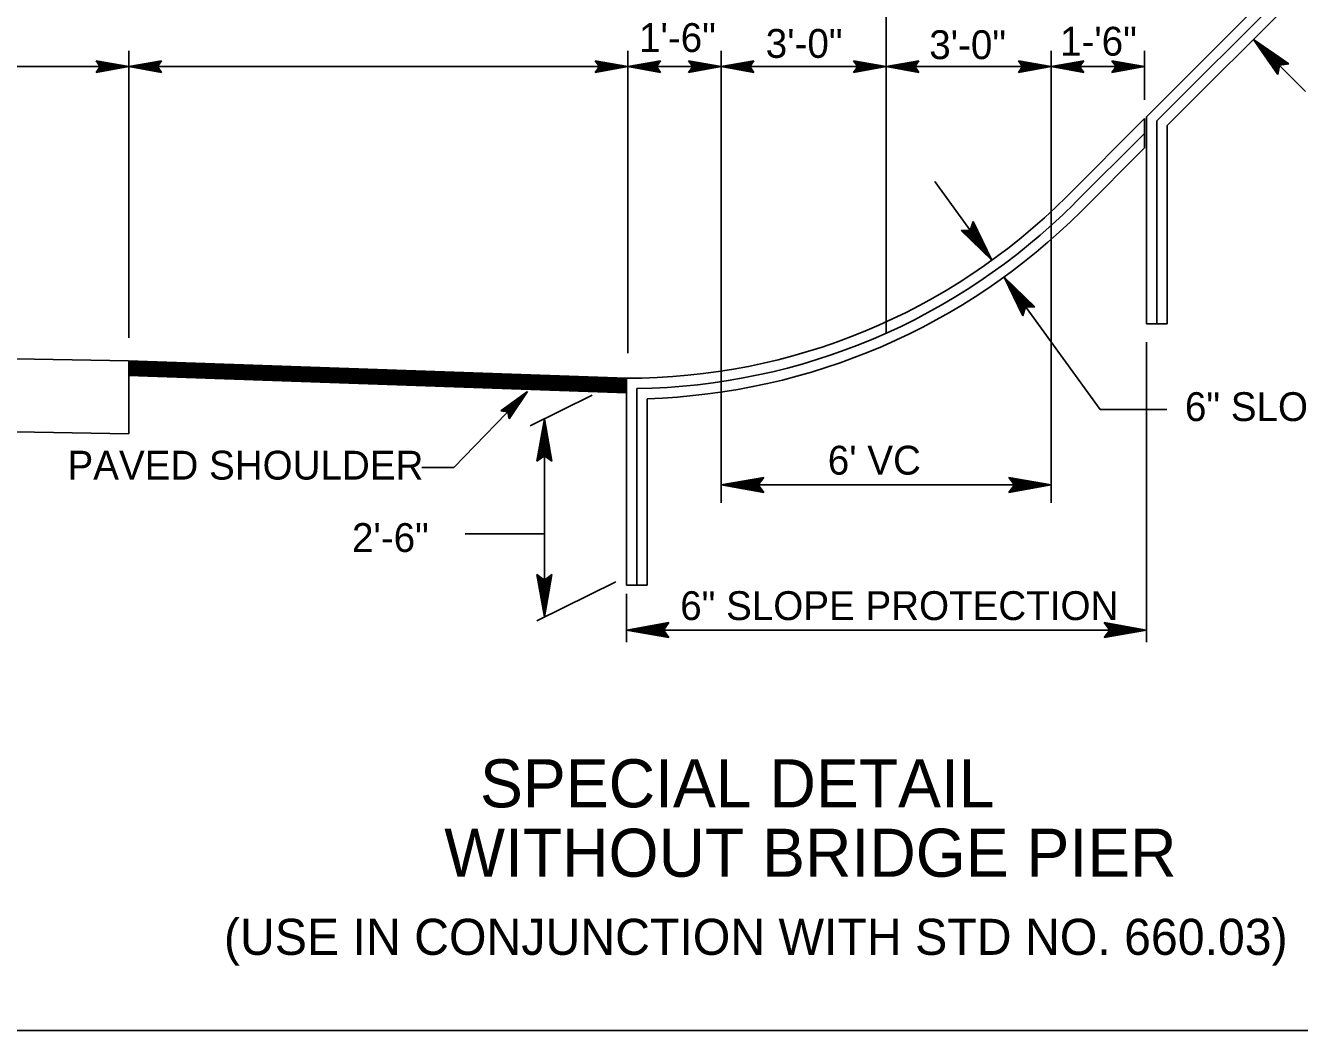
# Model space of a CAD drawing. Extents: x 1553195 to 1553792, y 810516 to 810787.
# Drawn here: x 1553751.08 to 1553774.26, y 810694.82 to 810713.11 of the extents above; entities that cross this region are included whole.
import ezdxf

# ---------------------------------------------------------------- set-up
doc = ezdxf.new("R2010")
doc.units = 0
doc.layers.add('Old_Level_28', color=7, linetype='Continuous')

msp = doc.modelspace()

# ---------------------------------------------------------------- linework, layer by layer
at = {"layer": 'Old_Level_28'}
for p, q in [((1553766.737, 810730.571), (1553766.737, 810707.494)), ((1553771.472, 810711.444), (1553773.92, 810713.892)), ((1553771.661, 810711.368), (1553774.055, 810713.761)), ((1553771.85, 810711.288), (1553774.188, 810713.623)), ((1553774.368, 810711.906), (1553773.419, 810712.852)), ((1553773.419, 810712.852), (1553774.061, 810712.408)), ((1553773.419, 810712.852), (1553773.866, 810712.213)), ((1553773.872, 810712.239), (1553773.419, 810712.852)), ((1553773.419, 810712.852), (1553773.872, 810712.262)), ((1553773.879, 810712.284), (1553773.419, 810712.852)), ((1553773.419, 810712.852), (1553773.881, 810712.308)), ((1553773.885, 810712.333), (1553773.419, 810712.852)), ((1553773.419, 810712.852), (1553773.888, 810712.357)), ((1553773.892, 810712.382), (1553773.419, 810712.852)), ((1553773.917, 810712.386), (1553773.419, 810712.852)), ((1553773.419, 810712.852), (1553773.941, 810712.386)), ((1553773.966, 810712.39), (1553773.419, 810712.852)), ((1553773.419, 810712.852), (1553773.988, 810712.396)), ((1553774.012, 810712.399), (1553773.419, 810712.852)), ((1553773.419, 810712.852), (1553774.037, 810712.402)), ((1553752.957, 810712.359), (1553752.363, 810712.461)), ((1553752.363, 810712.461), (1553752.439, 810712.359)), ((1553752.373, 810712.445), (1553752.957, 810712.359)), ((1553752.957, 810712.359), (1553752.383, 810712.432)), ((1553752.957, 810712.643), (1553752.957, 810707.421)), ((1553752.957, 810712.359), (1553753.552, 810712.461)), ((1553752.957, 810712.359), (1553753.539, 810712.445)), ((1553753.53, 810712.432), (1553752.957, 810712.359)), ((1553753.477, 810712.359), (1553753.552, 810712.461)), ((1553762.037, 810712.359), (1553761.444, 810712.461)), ((1553761.444, 810712.461), (1553761.519, 810712.359)), ((1553761.452, 810712.445), (1553762.037, 810712.359)), ((1553762.037, 810712.359), (1553761.464, 810712.432)), ((1553762.037, 810712.643), (1553762.037, 810707.145)), ((1553762.037, 810712.359), (1553762.633, 810712.461)), ((1553762.037, 810712.359), (1553762.619, 810712.445)), ((1553762.611, 810712.432), (1553762.037, 810712.359)), ((1553762.557, 810712.359), (1553762.633, 810712.461)), ((1553763.737, 810712.359), (1553763.143, 810712.461)), ((1553763.143, 810712.461), (1553763.219, 810712.359)), ((1553763.152, 810712.445), (1553763.737, 810712.359)), ((1553763.737, 810712.359), (1553763.164, 810712.432)), ((1553763.737, 810712.643), (1553763.737, 810704.421)), ((1553763.737, 810712.359), (1553764.332, 810712.461)), ((1553763.737, 810712.359), (1553764.319, 810712.445)), ((1553764.311, 810712.432), (1553763.737, 810712.359)), ((1553764.257, 810712.359), (1553764.332, 810712.461)), ((1553766.737, 810712.359), (1553766.143, 810712.461)), ((1553766.143, 810712.461), (1553766.219, 810712.359)), ((1553766.152, 810712.445), (1553766.737, 810712.359)), ((1553766.737, 810712.359), (1553766.164, 810712.432)), ((1553766.737, 810712.359), (1553767.332, 810712.461)), ((1553766.737, 810712.359), (1553767.319, 810712.445)), ((1553767.311, 810712.432), (1553766.737, 810712.359)), ((1553767.257, 810712.359), (1553767.332, 810712.461)), ((1553769.737, 810712.359), (1553769.143, 810712.461)), ((1553769.143, 810712.461), (1553769.219, 810712.359)), ((1553769.152, 810712.445), (1553769.737, 810712.359)), ((1553769.737, 810712.359), (1553769.164, 810712.432)), ((1553769.737, 810712.643), (1553769.737, 810704.421)), ((1553769.737, 810712.359), (1553770.332, 810712.461)), ((1553769.737, 810712.359), (1553770.319, 810712.445)), ((1553770.311, 810712.432), (1553769.737, 810712.359)), ((1553770.257, 810712.359), (1553770.332, 810712.461)), ((1553771.437, 810712.359), (1553770.843, 810712.461)), ((1553770.843, 810712.461), (1553770.92, 810712.359)), ((1553770.852, 810712.445), (1553771.437, 810712.359)), ((1553771.437, 810712.359), (1553770.864, 810712.432)), ((1553771.437, 810712.643), (1553771.437, 810711.754)), ((1553746.957, 810712.359), (1553752.957, 810712.359)), ((1553752.957, 810712.359), (1553752.363, 810712.252)), ((1553752.439, 810712.359), (1553752.363, 810712.252)), ((1553752.957, 810712.359), (1553752.373, 810712.268)), ((1553752.383, 810712.281), (1553752.957, 810712.359)), ((1553752.397, 810712.417), (1553752.957, 810712.359)), ((1553752.957, 810712.359), (1553752.397, 810712.297)), ((1553752.957, 810712.359), (1553752.406, 810712.402)), ((1553752.406, 810712.312), (1553752.957, 810712.359)), ((1553752.419, 810712.388), (1553752.957, 810712.359)), ((1553752.957, 810712.359), (1553752.419, 810712.326)), ((1553752.957, 810712.359), (1553752.43, 810712.372)), ((1553752.43, 810712.341), (1553752.957, 810712.359)), ((1553752.439, 810712.359), (1553752.957, 810712.359)), ((1553752.957, 810712.359), (1553753.519, 810712.417)), ((1553753.508, 810712.402), (1553752.957, 810712.359)), ((1553752.957, 810712.359), (1553753.497, 810712.388)), ((1553753.486, 810712.372), (1553752.957, 810712.359)), ((1553752.957, 810712.359), (1553753.552, 810712.252)), ((1553753.539, 810712.268), (1553752.957, 810712.359)), ((1553752.957, 810712.359), (1553753.53, 810712.281)), ((1553753.519, 810712.297), (1553752.957, 810712.359)), ((1553752.957, 810712.359), (1553753.508, 810712.312)), ((1553753.497, 810712.326), (1553752.957, 810712.359)), ((1553752.957, 810712.359), (1553753.486, 810712.341)), ((1553753.477, 810712.359), (1553752.957, 810712.359)), ((1553752.957, 810712.359), (1553762.037, 810712.359)), ((1553753.552, 810712.252), (1553753.477, 810712.359)), ((1553762.037, 810712.359), (1553761.444, 810712.252)), ((1553761.519, 810712.359), (1553761.444, 810712.252)), ((1553762.037, 810712.359), (1553761.452, 810712.268)), ((1553761.464, 810712.281), (1553762.037, 810712.359)), ((1553761.477, 810712.417), (1553762.037, 810712.359)), ((1553762.037, 810712.359), (1553761.477, 810712.297)), ((1553762.037, 810712.359), (1553761.486, 810712.402)), ((1553761.486, 810712.312), (1553762.037, 810712.359)), ((1553761.499, 810712.388), (1553762.037, 810712.359)), ((1553762.037, 810712.359), (1553761.499, 810712.326)), ((1553762.037, 810712.359), (1553761.51, 810712.372)), ((1553761.51, 810712.341), (1553762.037, 810712.359)), ((1553761.519, 810712.359), (1553762.037, 810712.359)), ((1553762.037, 810712.359), (1553762.599, 810712.417)), ((1553762.588, 810712.402), (1553762.037, 810712.359)), ((1553762.037, 810712.359), (1553762.577, 810712.388)), ((1553762.566, 810712.372), (1553762.037, 810712.359)), ((1553762.037, 810712.359), (1553763.737, 810712.359)), ((1553762.037, 810712.359), (1553762.633, 810712.252)), ((1553762.619, 810712.268), (1553762.037, 810712.359)), ((1553762.037, 810712.359), (1553762.611, 810712.281)), ((1553762.599, 810712.297), (1553762.037, 810712.359)), ((1553762.037, 810712.359), (1553762.588, 810712.312)), ((1553762.577, 810712.326), (1553762.037, 810712.359)), ((1553762.037, 810712.359), (1553762.566, 810712.341)), ((1553762.557, 810712.359), (1553762.037, 810712.359)), ((1553762.633, 810712.252), (1553762.557, 810712.359)), ((1553763.737, 810712.359), (1553763.143, 810712.252)), ((1553763.219, 810712.359), (1553763.143, 810712.252)), ((1553763.737, 810712.359), (1553763.152, 810712.268)), ((1553763.164, 810712.281), (1553763.737, 810712.359)), ((1553763.177, 810712.417), (1553763.737, 810712.359)), ((1553763.737, 810712.359), (1553763.177, 810712.297)), ((1553763.737, 810712.359), (1553763.185, 810712.402)), ((1553763.185, 810712.312), (1553763.737, 810712.359)), ((1553763.199, 810712.388), (1553763.737, 810712.359)), ((1553763.737, 810712.359), (1553763.199, 810712.326)), ((1553763.737, 810712.359), (1553763.21, 810712.372)), ((1553763.21, 810712.341), (1553763.737, 810712.359)), ((1553763.219, 810712.359), (1553763.737, 810712.359)), ((1553763.737, 810712.359), (1553764.299, 810712.417)), ((1553764.288, 810712.402), (1553763.737, 810712.359)), ((1553763.737, 810712.359), (1553764.277, 810712.388)), ((1553764.266, 810712.372), (1553763.737, 810712.359)), ((1553763.737, 810712.359), (1553766.737, 810712.359)), ((1553763.737, 810712.359), (1553764.332, 810712.252)), ((1553764.319, 810712.268), (1553763.737, 810712.359)), ((1553763.737, 810712.359), (1553764.311, 810712.281)), ((1553764.299, 810712.297), (1553763.737, 810712.359)), ((1553763.737, 810712.359), (1553764.288, 810712.312)), ((1553764.277, 810712.326), (1553763.737, 810712.359)), ((1553763.737, 810712.359), (1553764.266, 810712.341)), ((1553764.257, 810712.359), (1553763.737, 810712.359)), ((1553764.332, 810712.252), (1553764.257, 810712.359)), ((1553766.737, 810712.359), (1553766.143, 810712.252)), ((1553766.219, 810712.359), (1553766.143, 810712.252)), ((1553766.737, 810712.359), (1553766.152, 810712.268)), ((1553766.164, 810712.281), (1553766.737, 810712.359)), ((1553766.177, 810712.417), (1553766.737, 810712.359)), ((1553766.737, 810712.359), (1553766.177, 810712.297)), ((1553766.737, 810712.359), (1553766.185, 810712.402)), ((1553766.185, 810712.312), (1553766.737, 810712.359)), ((1553766.199, 810712.388), (1553766.737, 810712.359)), ((1553766.737, 810712.359), (1553766.199, 810712.326)), ((1553766.737, 810712.359), (1553766.21, 810712.372)), ((1553766.21, 810712.341), (1553766.737, 810712.359)), ((1553766.219, 810712.359), (1553766.737, 810712.359)), ((1553766.737, 810712.359), (1553767.299, 810712.417)), ((1553767.288, 810712.402), (1553766.737, 810712.359)), ((1553766.737, 810712.359), (1553767.277, 810712.388)), ((1553767.266, 810712.372), (1553766.737, 810712.359)), ((1553766.737, 810712.359), (1553769.737, 810712.359)), ((1553766.737, 810712.359), (1553767.332, 810712.252)), ((1553767.319, 810712.268), (1553766.737, 810712.359)), ((1553766.737, 810712.359), (1553767.311, 810712.281)), ((1553767.299, 810712.297), (1553766.737, 810712.359)), ((1553766.737, 810712.359), (1553767.288, 810712.312)), ((1553767.277, 810712.326), (1553766.737, 810712.359)), ((1553766.737, 810712.359), (1553767.266, 810712.341)), ((1553767.257, 810712.359), (1553766.737, 810712.359)), ((1553767.332, 810712.252), (1553767.257, 810712.359)), ((1553769.737, 810712.359), (1553769.143, 810712.252)), ((1553769.219, 810712.359), (1553769.143, 810712.252)), ((1553769.737, 810712.359), (1553769.152, 810712.268)), ((1553769.164, 810712.281), (1553769.737, 810712.359)), ((1553769.177, 810712.417), (1553769.737, 810712.359)), ((1553769.737, 810712.359), (1553769.177, 810712.297)), ((1553769.737, 810712.359), (1553769.185, 810712.402)), ((1553769.185, 810712.312), (1553769.737, 810712.359)), ((1553769.199, 810712.388), (1553769.737, 810712.359)), ((1553769.737, 810712.359), (1553769.199, 810712.326)), ((1553769.737, 810712.359), (1553769.21, 810712.372)), ((1553769.21, 810712.341), (1553769.737, 810712.359)), ((1553769.219, 810712.359), (1553769.737, 810712.359)), ((1553769.737, 810712.359), (1553770.299, 810712.417)), ((1553770.288, 810712.402), (1553769.737, 810712.359)), ((1553769.737, 810712.359), (1553770.277, 810712.388)), ((1553770.266, 810712.372), (1553769.737, 810712.359)), ((1553769.737, 810712.359), (1553771.437, 810712.359)), ((1553769.737, 810712.359), (1553770.332, 810712.252)), ((1553770.319, 810712.268), (1553769.737, 810712.359)), ((1553769.737, 810712.359), (1553770.311, 810712.281)), ((1553770.299, 810712.297), (1553769.737, 810712.359)), ((1553769.737, 810712.359), (1553770.288, 810712.312)), ((1553770.277, 810712.326), (1553769.737, 810712.359)), ((1553769.737, 810712.359), (1553770.266, 810712.341)), ((1553770.257, 810712.359), (1553769.737, 810712.359)), ((1553770.332, 810712.252), (1553770.257, 810712.359)), ((1553771.437, 810712.359), (1553770.843, 810712.252)), ((1553770.92, 810712.359), (1553770.843, 810712.252)), ((1553771.437, 810712.359), (1553770.852, 810712.268)), ((1553770.864, 810712.281), (1553771.437, 810712.359)), ((1553770.877, 810712.417), (1553771.437, 810712.359)), ((1553771.437, 810712.359), (1553770.877, 810712.297)), ((1553771.437, 810712.359), (1553770.885, 810712.402)), ((1553770.885, 810712.312), (1553771.437, 810712.359)), ((1553770.899, 810712.388), (1553771.437, 810712.359)), ((1553771.437, 810712.359), (1553770.899, 810712.326)), ((1553771.437, 810712.359), (1553770.91, 810712.372)), ((1553770.91, 810712.341), (1553771.437, 810712.359)), ((1553770.92, 810712.359), (1553771.437, 810712.359)), ((1553773.866, 810712.213), (1553773.892, 810712.382)), ((1553773.892, 810712.382), (1553774.061, 810712.408)), ((1553770.024, 810709.995), (1553771.437, 810711.41)), ((1553771.437, 810711.41), (1553771.437, 810710.877)), ((1553771.472, 810711.444), (1553771.472, 810707.679)), ((1553771.661, 810711.368), (1553771.661, 810707.679)), ((1553771.85, 810711.288), (1553771.85, 810707.679)), ((1553770.159, 810709.864), (1553771.437, 810711.141)), ((1553770.29, 810709.728), (1553771.437, 810710.877)), ((1553768.661, 810708.832), (1553767.624, 810710.266)), ((1553768.319, 810709.539), (1553768.266, 810709.375)), ((1553768.283, 810709.424), (1553768.661, 810708.832)), ((1553768.661, 810708.832), (1553768.29, 810709.448)), ((1553768.299, 810709.468), (1553768.661, 810708.832)), ((1553768.661, 810708.832), (1553768.304, 810709.49)), ((1553768.312, 810709.515), (1553768.661, 810708.832)), ((1553768.661, 810708.832), (1553768.319, 810709.539)), ((1553768.661, 810708.832), (1553768.099, 810709.375)), ((1553768.266, 810709.375), (1553768.099, 810709.375)), ((1553768.661, 810708.832), (1553768.123, 810709.375)), ((1553768.146, 810709.375), (1553768.661, 810708.832)), ((1553768.661, 810708.832), (1553768.171, 810709.375)), ((1553768.197, 810709.375), (1553768.661, 810708.832)), ((1553768.661, 810708.832), (1553768.219, 810709.375)), ((1553768.246, 810709.375), (1553768.661, 810708.832)), ((1553768.266, 810709.375), (1553768.661, 810708.832)), ((1553768.661, 810708.832), (1553768.277, 810709.399)), ((1553770.628, 810706.119), (1553768.884, 810708.528)), ((1553768.884, 810708.528), (1553769.445, 810707.983)), ((1553768.884, 810708.528), (1553769.224, 810707.823)), ((1553769.233, 810707.848), (1553768.884, 810708.528)), ((1553768.884, 810708.528), (1553769.239, 810707.868)), ((1553769.248, 810707.894), (1553768.884, 810708.528)), ((1553768.884, 810708.528), (1553769.253, 810707.917)), ((1553769.263, 810707.934), (1553768.884, 810708.528)), ((1553768.884, 810708.528), (1553769.27, 810707.962)), ((1553769.275, 810707.986), (1553768.884, 810708.528)), ((1553769.301, 810707.983), (1553768.884, 810708.528)), ((1553768.884, 810708.528), (1553769.324, 810707.983)), ((1553769.35, 810707.983), (1553768.884, 810708.528)), ((1553768.884, 810708.528), (1553769.37, 810707.983)), ((1553769.397, 810707.983), (1553768.884, 810708.528)), ((1553768.884, 810708.528), (1553769.419, 810707.983)), ((1553769.224, 810707.823), (1553769.275, 810707.986)), ((1553769.275, 810707.986), (1553769.445, 810707.983)), ((1553771.472, 810707.679), (1553771.85, 810707.679)), ((1553771.472, 810707.341), (1553771.472, 810701.881)), ((1553746.957, 810707.115), (1553752.95, 810707.004)), ((1553752.95, 810707.004), (1553762.012, 810706.686)), ((1553752.957, 810705.672), (1553752.957, 810707.012)), ((1553752.957, 810706.995), (1553762.01, 810706.679)), ((1553752.957, 810706.981), (1553762.01, 810706.666)), ((1553752.957, 810706.966), (1553762.01, 810706.65)), ((1553752.957, 810706.952), (1553762.01, 810706.637)), ((1553752.957, 810706.937), (1553762.01, 810706.621)), ((1553752.957, 810706.923), (1553762.01, 810706.606)), ((1553752.957, 810706.901), (1553762.01, 810706.585)), ((1553752.957, 810706.881), (1553762.01, 810706.565)), ((1553752.957, 810706.861), (1553762.01, 810706.546)), ((1553752.957, 810706.841), (1553762.006, 810706.526)), ((1553752.957, 810706.826), (1553762.006, 810706.51)), ((1553752.957, 810706.806), (1553762.006, 810706.488)), ((1553752.957, 810706.788), (1553762.006, 810706.473)), ((1553752.957, 810706.777), (1553762.006, 810706.461)), ((1553752.957, 810706.763), (1553762.003, 810706.448)), ((1553752.957, 810706.753), (1553762.003, 810706.435)), ((1553752.957, 810706.741), (1553762.002, 810706.425)), ((1553752.957, 810706.735), (1553762.01, 810706.419)), ((1553762.01, 810706.688), (1553762.01, 810706.435)), ((1553762.01, 810706.688), (1553762.01, 810702.919)), ((1553758.87, 810705.059), (1553760.214, 810706.445)), ((1553760.214, 810706.445), (1553759.724, 810706.092)), ((1553759.744, 810706.088), (1553760.214, 810706.445)), ((1553760.214, 810706.445), (1553759.761, 810706.086)), ((1553759.777, 810706.083), (1553760.214, 810706.445)), ((1553760.214, 810706.445), (1553759.797, 810706.083)), ((1553759.815, 810706.079), (1553760.214, 810706.445)), ((1553760.214, 810706.445), (1553759.835, 810706.079)), ((1553759.852, 810706.073), (1553760.214, 810706.445)), ((1553759.855, 810706.054), (1553760.214, 810706.445)), ((1553760.214, 810706.445), (1553759.861, 810706.039)), ((1553759.864, 810706.019), (1553760.214, 810706.445)), ((1553760.214, 810706.445), (1553759.866, 810706.001)), ((1553759.868, 810705.981), (1553760.214, 810706.445)), ((1553760.214, 810706.445), (1553759.875, 810705.946)), ((1553760.214, 810706.445), (1553759.875, 810705.963)), ((1553762.199, 810706.499), (1553762.199, 810702.919)), ((1553761.386, 810706.379), (1553760.257, 810705.819)), ((1553762.39, 810706.314), (1553762.39, 810702.919)), ((1553759.724, 810706.092), (1553759.852, 810706.073)), ((1553759.852, 810706.073), (1553759.875, 810705.946)), ((1553760.519, 810705.948), (1553760.383, 810705.179)), ((1553760.403, 810705.193), (1553760.519, 810705.948)), ((1553760.519, 810705.948), (1553760.422, 810705.201)), ((1553760.439, 810705.219), (1553760.519, 810705.948)), ((1553760.519, 810705.948), (1553760.459, 810705.235)), ((1553760.479, 810705.248), (1553760.519, 810705.948)), ((1553760.519, 810705.948), (1553760.499, 810705.263)), ((1553760.519, 810702.343), (1553760.519, 810705.948)), ((1553760.519, 810705.948), (1553760.657, 810705.179)), ((1553760.519, 810705.277), (1553760.519, 810705.948)), ((1553760.539, 810705.263), (1553760.519, 810705.948)), ((1553760.519, 810705.948), (1553760.559, 810705.248)), ((1553760.579, 810705.235), (1553760.519, 810705.948)), ((1553760.519, 810705.948), (1553760.597, 810705.219)), ((1553760.617, 810705.201), (1553760.519, 810705.948)), ((1553760.519, 810705.948), (1553760.634, 810705.193)), ((1553771.846, 810706.119), (1553770.628, 810706.119)), ((1553746.968, 810705.786), (1553752.959, 810705.675)), ((1553760.383, 810705.179), (1553760.519, 810705.277)), ((1553760.519, 810705.277), (1553760.657, 810705.179)), ((1553758.87, 810705.059), (1553758.29, 810705.059)), ((1553763.737, 810704.746), (1553764.51, 810704.881)), ((1553763.737, 810704.746), (1553764.497, 810704.861)), ((1553764.484, 810704.841), (1553763.737, 810704.746)), ((1553763.737, 810704.746), (1553764.468, 810704.822)), ((1553764.452, 810704.801), (1553763.737, 810704.746)), ((1553763.737, 810704.746), (1553764.439, 810704.783)), ((1553764.41, 810704.746), (1553764.51, 810704.881)), ((1553769.737, 810704.746), (1553768.968, 810704.881)), ((1553768.968, 810704.881), (1553769.07, 810704.746)), ((1553768.982, 810704.861), (1553769.737, 810704.746)), ((1553769.737, 810704.746), (1553768.995, 810704.841)), ((1553769.01, 810704.822), (1553769.737, 810704.746)), ((1553769.737, 810704.746), (1553769.025, 810704.801)), ((1553769.039, 810704.786), (1553769.737, 810704.746)), ((1553764.423, 810704.763), (1553763.737, 810704.746)), ((1553763.737, 810704.746), (1553769.737, 810704.746)), ((1553763.737, 810704.746), (1553764.51, 810704.608)), ((1553764.497, 810704.628), (1553763.737, 810704.746)), ((1553763.737, 810704.746), (1553764.484, 810704.65)), ((1553764.468, 810704.666), (1553763.737, 810704.746)), ((1553763.737, 810704.746), (1553764.452, 810704.688)), ((1553764.439, 810704.704), (1553763.737, 810704.746)), ((1553763.737, 810704.746), (1553764.423, 810704.724)), ((1553764.41, 810704.746), (1553763.737, 810704.746)), ((1553764.51, 810704.608), (1553764.41, 810704.746)), ((1553769.737, 810704.746), (1553768.968, 810704.608)), ((1553769.07, 810704.746), (1553768.968, 810704.608)), ((1553769.737, 810704.746), (1553768.982, 810704.628)), ((1553768.995, 810704.65), (1553769.737, 810704.746)), ((1553769.737, 810704.746), (1553769.01, 810704.666)), ((1553769.025, 810704.688), (1553769.737, 810704.746)), ((1553769.737, 810704.746), (1553769.039, 810704.705)), ((1553769.737, 810704.746), (1553769.057, 810704.763)), ((1553769.057, 810704.724), (1553769.737, 810704.746)), ((1553769.07, 810704.746), (1553769.737, 810704.746)), ((1553759.079, 810703.856), (1553760.519, 810703.856)), ((1553761.817, 810702.983), (1553760.379, 810702.272)), ((1553760.519, 810702.343), (1553760.383, 810703.115)), ((1553760.519, 810703.01), (1553760.383, 810703.115)), ((1553760.519, 810702.343), (1553760.403, 810703.099)), ((1553760.422, 810703.086), (1553760.519, 810702.343)), ((1553760.519, 810702.343), (1553760.439, 810703.068)), ((1553760.459, 810703.053), (1553760.519, 810702.343)), ((1553760.519, 810702.343), (1553760.484, 810703.041)), ((1553760.499, 810703.025), (1553760.519, 810702.343)), ((1553760.519, 810702.343), (1553760.657, 810703.115)), ((1553760.657, 810703.115), (1553760.519, 810703.01)), ((1553760.634, 810703.099), (1553760.519, 810702.343)), ((1553760.519, 810702.343), (1553760.617, 810703.086)), ((1553760.597, 810703.068), (1553760.519, 810702.343)), ((1553760.519, 810702.343), (1553760.579, 810703.053)), ((1553760.559, 810703.039), (1553760.519, 810702.343)), ((1553760.519, 810702.343), (1553760.539, 810703.025)), ((1553760.519, 810703.01), (1553760.519, 810702.343)), ((1553762.01, 810702.919), (1553762.39, 810702.919)), ((1553762.01, 810702.766), (1553762.01, 810701.881)), ((1553762.01, 810702.103), (1553762.784, 810702.239)), ((1553762.683, 810702.103), (1553762.784, 810702.239)), ((1553771.472, 810702.103), (1553770.703, 810702.239)), ((1553770.703, 810702.239), (1553770.806, 810702.103)), ((1553762.01, 810702.103), (1553762.77, 810702.219)), ((1553762.757, 810702.199), (1553762.01, 810702.103)), ((1553762.01, 810702.103), (1553762.741, 810702.179)), ((1553762.726, 810702.159), (1553762.01, 810702.103)), ((1553762.01, 810702.103), (1553762.712, 810702.141)), ((1553762.697, 810702.121), (1553762.01, 810702.103)), ((1553762.01, 810702.103), (1553771.472, 810702.103)), ((1553762.01, 810702.103), (1553762.784, 810701.966)), ((1553762.77, 810701.986), (1553762.01, 810702.103)), ((1553762.01, 810702.103), (1553762.757, 810702.008)), ((1553762.741, 810702.024), (1553762.01, 810702.103)), ((1553762.01, 810702.103), (1553762.726, 810702.046)), ((1553762.712, 810702.061), (1553762.01, 810702.103)), ((1553762.01, 810702.103), (1553762.697, 810702.081)), ((1553762.683, 810702.103), (1553762.01, 810702.103)), ((1553762.784, 810701.966), (1553762.683, 810702.103)), ((1553771.472, 810702.103), (1553770.703, 810701.966)), ((1553770.806, 810702.103), (1553770.703, 810701.966)), ((1553770.717, 810702.219), (1553771.472, 810702.103)), ((1553771.472, 810702.103), (1553770.717, 810701.986)), ((1553771.472, 810702.103), (1553770.731, 810702.199)), ((1553770.731, 810702.008), (1553771.472, 810702.103)), ((1553770.745, 810702.179), (1553771.472, 810702.103)), ((1553771.472, 810702.103), (1553770.745, 810702.024)), ((1553771.472, 810702.103), (1553770.761, 810702.159)), ((1553770.761, 810702.046), (1553771.472, 810702.103)), ((1553770.774, 810702.144), (1553771.472, 810702.103)), ((1553771.472, 810702.103), (1553770.774, 810702.063)), ((1553771.472, 810702.103), (1553770.793, 810702.121)), ((1553770.793, 810702.081), (1553771.472, 810702.103)), ((1553770.806, 810702.103), (1553771.472, 810702.103))]:
    msp.add_line(p, q, dxfattribs=at)
msp.add_lwpolyline([(1553739.439, 810764.018), (1553791.973, 810764.018), (1553791.973, 810694.817), (1553739.439, 810694.817)], close=True, dxfattribs=at)
for radius, start in [(11.295, 269.8759), (11.483, 270.8173), (11.672, 271.7285)]:
    msp.add_arc((1553762.036, 810717.981), radius, start, 314.9996, dxfattribs=at)

# ---------------------------------------------------------------- texts
for s, height, p in [('1\'-6"', 0.5249, (1553762.241, 810712.623)), ('3\'-0"', 0.5249, (1553764.546, 810712.516)), ('3\'-0"', 0.5249, (1553767.521, 810712.493)), ('1-\'6"', 0.5249, (1553769.901, 810712.556)), ('6" SLOPE PROTECTION (ROADWAY ITEM)', 0.52493, (1553772.173, 810705.907)), ('PAVED SHOULDER', 0.52493, (1553751.842, 810704.842)), ("6' VC", 0.5249, (1553765.675, 810704.933)), ('2\'-6"', 0.5249, (1553757.018, 810703.525)), ('6" SLOPE PROTECTION', 0.52493, (1553762.99, 810702.286)), ('  SPECIAL DETAIL', 0.87489, (1553758.697, 810698.878)), ('WITHOUT BRIDGE PIER', 0.87489, (1553758.697, 810697.615)), ('(USE IN CONJUNCTION WITH STD NO. 660.03)', 0.65617, (1553754.688, 810696.194))]:
    msp.add_text(s, height=height, dxfattribs=at).set_placement(p)

doc.saveas('drawing.dxf')
